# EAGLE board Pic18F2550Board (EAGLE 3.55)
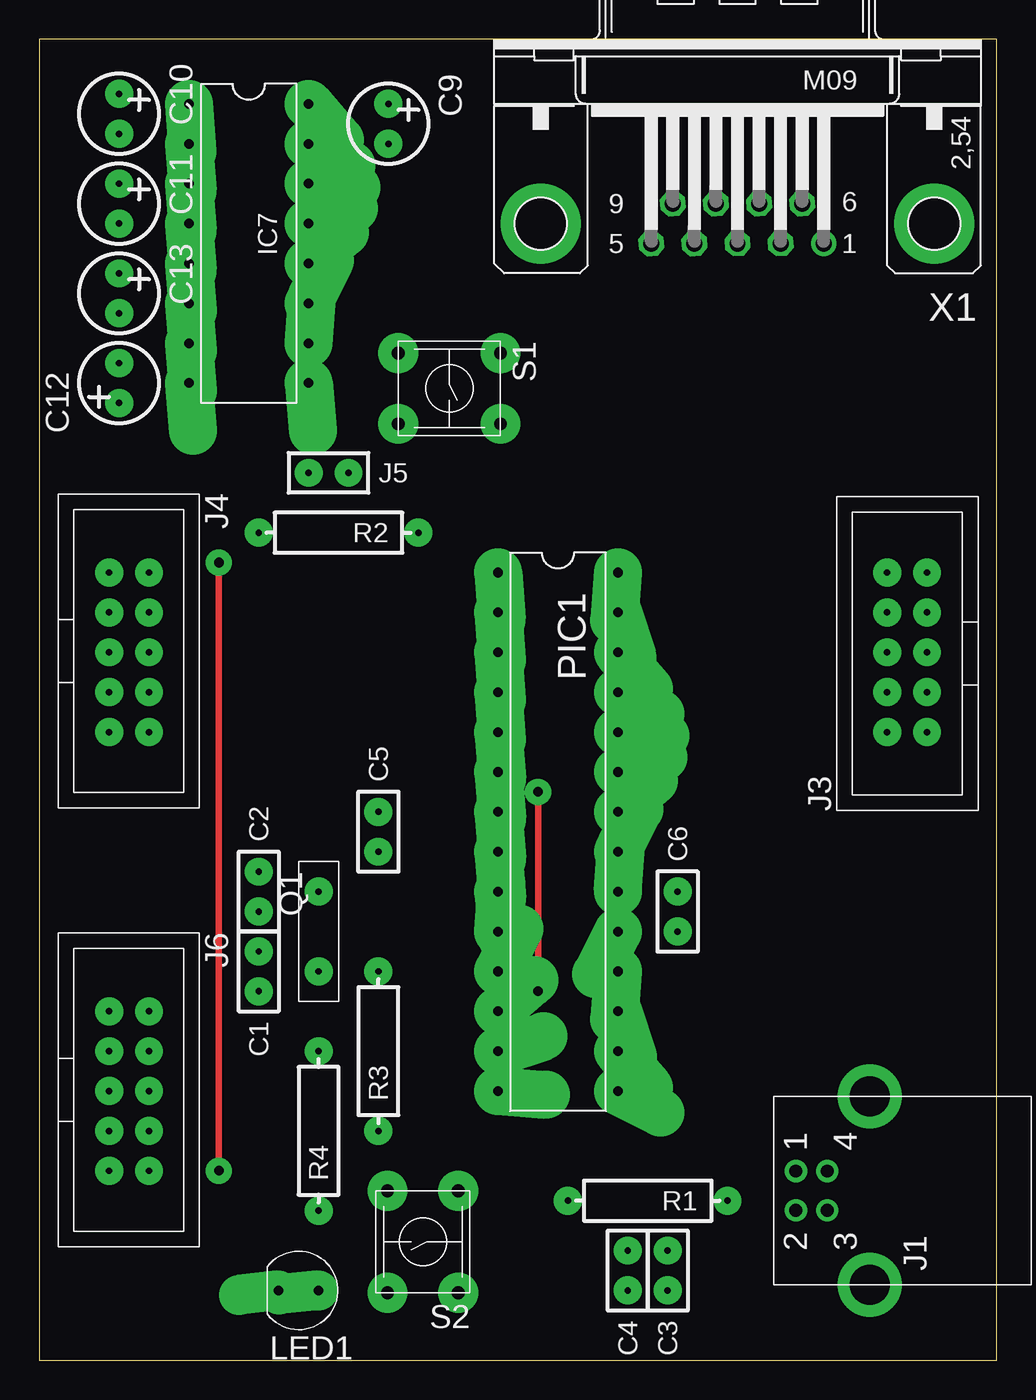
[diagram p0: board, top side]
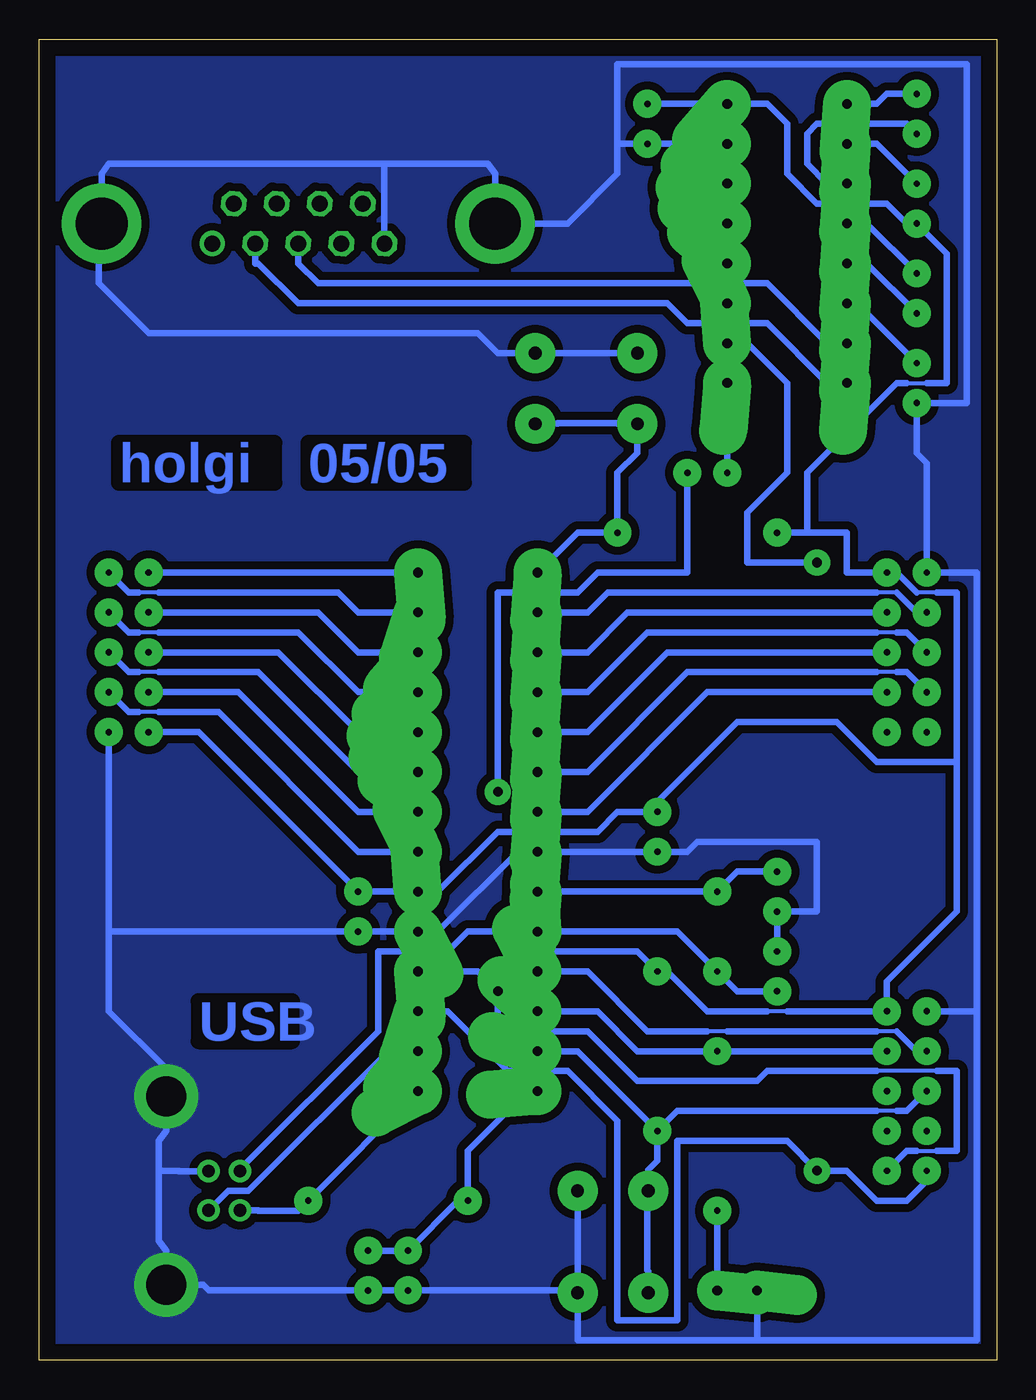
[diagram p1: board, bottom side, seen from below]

Size 60.94 x 84.12 mm. Coordinates in mm from the lower left corner, seen from the top.
Outline: 0,0 60.94,0 60.94,84.12 0,84.12 0,0
Copper layers used: Top, Bottom

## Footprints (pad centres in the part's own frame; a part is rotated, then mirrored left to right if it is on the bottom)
RM2,5 = drill 0.406 pad 1.778 round:  -1.27,0;  1.27,0
KO01 = drill 0.406 pad 1.778 round:  -1.27,0;  1.27,0
L-16B = drill 0.61 pad 3.048 offset:  -8.89,-3.81;  -6.35,-3.81;  6.35,-3.81;  8.89,-3.81;  -3.81,-3.81;  -1.27,-3.81;  3.81,-3.81;  1.27,-3.81;  8.89,3.81;  6.35,3.81;  3.81,3.81;  1.27,3.81;  -1.27,3.81;  -3.81,3.81;  -6.35,3.81;  -8.89,3.81
B_B = drill 2.54 pad 4.064 round: 1 6,-2.7; 2 -6,-2.7 | drill 0.813 pad 1.422 round:  1.25,0;  -1.25,0;  1.25,2;  -1.25,2
5 = drill 0.406 pad 1.778 round:  0,0;  2.54,0;  5.08,0;  7.62,0;  10.16,0;  10.16,2.54;  7.62,2.54;  5.08,2.54;  2.54,2.54;  0,2.54
MPER = drill 0.406 pad 1.778 round:  -1.27,0;  1.27,0
D_5MM = drill 0.61 pad 2.54 offset:  -1.27,0;  1.27,0
L-28SB = drill 0.61 pad 3.048 offset:  0,0;  2.54,0;  15.24,0;  17.78,0;  5.08,0;  7.62,0;  12.7,0;  10.16,0;  20.32,0;  22.86,0;  25.4,0;  27.94,0;  30.48,0;  33.02,0;  33.02,7.62;  30.48,7.62;  27.94,7.62;  25.4,7.62;  22.86,7.62;  20.32,7.62;  17.78,7.62;  15.24,7.62;  12.7,7.62;  10.16,7.62;  7.62,7.62;  5.08,7.62;  2.54,7.62;  0,7.62
ARZ_ST = drill 0.406 pad 1.778 round:  -2.54,0;  2.54,0
S04 = drill 0.406 pad 1.778 round:  -5.08,0;  5.08,0
US = drill 0.813 pad 2.54 round:  0,0;  4.5,0;  4.5,6.5;  0,6.5
9HP = drill 1.016 pad 1.6 octagon:  5.486,1.27;  2.743,1.27;  0,1.27;  -2.743,1.27;  4.115,-1.27;  1.372,-1.27;  -1.372,-1.27;  -4.115,-1.27 | drill 1.016 pad 1.6 round:  -5.486,1.27 | drill 3.302 pad 5.08 round:  -12.522,0;  12.522,0

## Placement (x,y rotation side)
C1  15p  [RM2,5]  13.97,24.77 270 top
C2  15p  [RM2,5]  13.97,29.84 90 top
C3  100n  [RM2,5]  40.01,5.71 270 top
C4  100n  [RM2,5]  37.47,5.71 270 top
C5  100n  [RM2,5]  21.59,33.66 90 top
C6  100n  [RM2,5]  40.64,28.57 90 top
C9  10u  [KO01]  22.23,78.74 270 top
C10  1u  [KO01]  5.08,79.38 270 top
C11  1u  [KO01]  5.08,73.66 270 top
C12  1u  [KO01]  5.08,62.23 90 top
C13  1u  [KO01]  5.08,67.94 270 top
IC7  MAX232  [L-16B]  13.34,71.12 270 top
J1  USB_B  [B_B]  50.16,10.79 90 top
J3  8BITPORT  [5]  56.52,40.01 90 top
J4  8BITPORT  [5]  4.45,50.16 270 top
J5  JUMPER  [MPER]  18.41,56.52 0 top
J6  8BITPORT  [5]  4.45,22.23 270 top
LED1  red  [D_5MM]  16.51,4.45 180 top
PIC1  18F2550  [L-28SB]  29.21,50.16 270 top
Q1  20.0MHz  [ARZ_ST]  17.78,27.3 270 top
R1  1k5  [S04]  38.73,10.16 180 top
R2  10k  [S04]  19.05,52.7 180 top
R3  47k  [S04]  21.59,19.68 90 top
R4  1k  [S04]  17.78,14.61 90 top
S1  Reset  [US]  22.86,64.14 270 top
S2  BOOTLOAD  [US]  26.67,10.79 180 top
X1  M09HP  [9HP]  44.45,72.39 180 top

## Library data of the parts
C1-C6 J3-J6 LED1 PIC1 Q1 R1-R4 S1 S2 = holg_plt
C9-C13 = holgnorm
IC7 = maxim
J1 = 8031bord
X1 = subd-a

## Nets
+5V: C5. C6. C9. C11. IC7. J1. J3. J4. J6. PIC1. R2. R3.
GND: C1. C2. C3. C4. C5. C6. C9. C12. IC7. J1. J1.1 J1.2 J3. J4. J6. LED1. PIC1. S1. S2. X1.
N$1: C3. C4. PIC1. R1.
N$2: C12. IC7.
N$3: C2. PIC1. Q1.
N$4: C1. PIC1. Q1.
N$7: LED1. R4.
N$8: J1. PIC1. R1.
N$9: J1. PIC1.
N$15: J3. PIC1.
N$16: PIC1. R2. S1.
N$17: J3. PIC1.
N$18: J3. PIC1.
N$19: J3. PIC1.
N$20: J3. PIC1.
N$21: J3. PIC1.
N$22: J3. PIC1.
N$23: J3. PIC1.
N$24: C11. IC7.
N$25: C10. IC7.
N$26: C13. IC7.
N$27: C10. IC7.
N$28: C13. IC7.
N$29: J4. PIC1.
N$30: J4. PIC1.
N$31: J4. PIC1.
N$32: J4. PIC1.
N$33: J4. PIC1.
N$34: J4. PIC1.
N$35: IC7. J5.
RC0: J6. PIC1.
RC1: J6. PIC1. R4.
RC2: J6. PIC1. R3. S2.
RXD: J5. J6. PIC1.
RXD_IN: IC7. X1.
TXD: IC7. J6. PIC1.
TXD_OUT: IC7. X1.

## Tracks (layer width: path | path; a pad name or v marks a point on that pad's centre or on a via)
+5V
  Bottom 0.254: 5.71,62.23 4.45,62.23 | 3.81,48.9 5.08,48.9 | 13.34,22.23 14.61,22.23
  Bottom 0.406: 22.23,80.01 IC7. 14.61,80.01 13.34,78.74 13.34,75.56 11.43,73.66 6.99,73.66 5.71,72.39 C11. 3.17,70.48 3.17,62.23 4.45,62.23 | 5.71,62.23 6.35,62.23 12.06,56.52 12.06,52.7 | 12.06,52.7 9.53,52.7 9.53,50.16 J4. 6.35,50.16 5.08,48.9 | 12.06,52.7 R2. | 3.81,48.9 2.54,48.9 2.54,38.1 | 2.54,38.1 2.54,28.57 6.99,24.13 J6. 13.34,22.23 | 2.54,38.1 7.62,38.1 10.16,40.64 16.51,40.64 21.59,35.56 C5. 24.13,34.92 25.4,33.66 31.75,33.66 35.56,29.84 36.83,29.84 C6. 50.8,40.01 J3. | 14.61,22.23 18.41,22.23 20.95,24.77 R3. 22.86,26.04 30.48,26.04 31.75,27.3 33.66,27.3 34.92,26.04 39.37,26.04 39.37,20.95 48.16,12.16 48.16,12.04
GND
  Bottom 0.406: 13.97,26.04 13.97,28.57 11.43,28.57 11.43,33.02 19.05,33.02 19.68,32.38 21.59,32.38 29.21,32.38 30.48,32.38 35.56,27.3 36.83,27.3 40.64,27.3 56.52,27.3 | 50.16,12.04 52.07,12.04 52.07,12.06 53.34,12.06 | 53.34,12.06 53.34,13.97 52.87,14.61 J1.1 52.87,18.57 56.52,22.23 56.52,27.3 | 17.14,77.47 C9. 24.13,77.47 | 24.13,77.47 24.13,82.55 1.91,82.55 1.91,60.96 5.08,60.96 5.08,57.78 4.45,57.15 4.45,50.16 1.27,50.16 1.27,22.23 | 24.13,77.47 24.13,75.56 27.3,72.39 X1. 31.93,75.56 32.38,76.2 38.73,76.2 | 38.96,71.12 38.96,76.2 38.73,76.2 | 38.73,76.2 56.52,76.2 56.97,75.56 56.97,72.39 56.97,70.03 57.15,69.85 57.15,68.58 53.98,65.41 33.02,65.41 31.75,64.14 S1. 22.86,64.14 | 53.34,12.06 53.34,7.62 52.87,6.99 J1.2 50.52,4.79 50.16,4.45 C3. C4. 27.94,4.45 27.79,4.29 S2. | 1.27,22.23 4.45,22.23 | S2. 26.67,10.79 | S2. 26.67,1.27 15.24,1.27 | 15.24,1.27 LED1. | 1.27,22.23 1.27,1.27 15.24,1.27 | 56.52,27.3 56.52,40.01
  pour Bottom (isolate 0.508): 0.64,0.64 0.64,83.19 60.33,83.19 60.33,0.64
N$1
  Bottom 0.406: 40.01,6.99 37.47,6.99 34.29,10.16 R1. 33.66,13.34 29.84,17.14 29.21,17.14
N$2
  Bottom 0.406: 9.53,67.31 8.89,67.31 C12.
N$3
  Bottom 0.406: C2. 16.51,31.11 17.78,29.84 29.21,29.84
N$4
  Bottom 0.406: C1. 16.51,23.5 Q1. 20.32,27.3 29.21,27.3
N$7
  Bottom 0.406: 17.78,4.45 17.78,9.53
N$8
  Bottom 0.406: 36.83,17.14 43.81,10.16 44.45,9.53 46.99,9.53 47.01,9.54 J1.
N$9
  Bottom 0.406: 50.16,9.54 50.15,9.54 48.9,10.79 47.62,10.79 38.73,19.68 36.83,19.68
N$15
  Bottom 0.406: PIC1. 53.98,50.16
N$16
  Bottom 0.406: 29.36,59.63 27.94,59.63 27.94,59.69 24.13,59.69 24.13,59.63 22.86,59.63 22.86,57.78 24.13,56.52 24.13,52.7 26.67,52.7 29.21,50.16
N$17
  Bottom 0.254: 53.34,48.9 54.61,48.9
  Bottom 0.406: 56.52,50.16 55.24,48.9 54.61,48.9 | 36.83,47.62 40.64,47.62 41.91,48.9 53.34,48.9
N$18
  Bottom 0.406: 36.83,45.09 40.64,45.09 43.18,47.62 53.98,47.62
N$19
  Bottom 0.254: 53.34,46.35 54.61,46.35
  Bottom 0.406: 36.83,42.55 40.64,42.55 44.45,46.35 53.34,46.35 | 56.52,47.62 55.24,46.35 54.61,46.35
N$20
  Bottom 0.406: 36.83,40.01 40.64,40.01 45.72,45.09 53.98,45.09
N$21
  Bottom 0.254: 53.34,43.81 54.61,43.81
  Bottom 0.406: 56.52,45.09 55.24,43.81 54.61,43.81 | 36.83,37.47 40.64,37.47 46.99,43.81 53.34,43.81
N$22
  Bottom 0.406: 36.83,34.92 40.64,34.92 48.26,42.55 53.98,42.55
N$23
  Bottom 0.254: 53.34,41.27 54.61,41.27
  Bottom 0.406: 56.52,42.55 55.24,41.27 54.61,41.27 | 36.83,32.38 40.64,32.38 49.53,41.27 53.34,41.27
N$24
  Bottom 0.406: 9.53,77.47 7.62,77.47 5.08,74.93
N$25
  Bottom 0.406: 9.53,74.93 10.79,74.93 12.06,76.2 12.06,78.11 11.43,78.74 5.71,78.74 C10.
N$26
  Bottom 0.406: 9.53,69.85 8.26,69.85 C13.
N$27
  Bottom 0.406: 9.53,80.01 7.62,80.01 6.99,80.64 5.08,80.64
N$28
  Bottom 0.406: 9.53,72.39 8.26,72.39 5.08,69.22
N$29
  Bottom 0.254: 6.35,48.9 7.62,48.9
  Bottom 0.406: 29.21,47.62 26.04,47.62 24.77,48.9 7.62,48.9 | 4.45,47.62 5.08,47.62 6.35,48.9
N$30
  Bottom 0.406: 29.21,45.09 26.04,45.09 23.5,47.62 6.99,47.62
N$31
  Bottom 0.254: 6.35,46.35 7.62,46.35
  Bottom 0.406: 4.45,45.09 5.71,46.35 6.35,46.35 | 29.21,42.55 26.04,42.55 22.23,46.35 7.62,46.35
N$32
  Bottom 0.406: 6.99,45.09 20.95,45.09 26.04,40.01 29.21,40.01
N$33
  Bottom 0.254: 6.35,43.81 7.62,43.81
  Bottom 0.406: 4.45,42.55 5.71,43.81 6.35,43.81 | 29.21,37.47 26.04,37.47 19.68,43.81 7.62,43.81
N$34
  Bottom 0.406: 29.21,34.92 26.04,34.92 18.41,42.55 6.99,42.55
N$35
  Bottom 0.406: 17.14,56.52 17.14,62.23
RC0
  Bottom 0.254: 6.35,20.95 7.62,20.95 | 17.14,20.95 18.41,20.95
  Bottom 0.406: 4.45,19.68 5.08,19.68 6.35,20.95 | 29.21,24.77 26.04,24.77 22.23,20.95 18.41,20.95 | 7.62,20.95 17.14,20.95
RC1
  Bottom 0.406: 6.99,19.68 R4. 22.86,19.68 25.4,22.23 29.21,22.23
RC2
  Bottom 0.254: 6.35,15.88 7.62,15.88
  Bottom 0.406: 4.45,17.14 5.71,15.88 6.35,15.88 | 21.59,14.61 20.32,15.88 7.62,15.88 | 29.21,19.68 26.67,19.68 21.59,14.61 | 21.59,14.61 21.59,12.7 22.17,12.12 22.17,10.79 22.17,9.58 22.23,9.53 22.23,5.71 22.17,5.66 22.17,4.29
RXD  (via drill 0.61 pad 1.68)
  Top 0.406: v31.75,23.5 v31.75,36.2
  Bottom 0.254: 3.81,18.41 7.62,18.41 | 5.08,13.34 3.81,13.34
  Bottom 0.406: 36.83,24.77 33.02,24.77 v31.75,23.5 31.75,20.95 26.04,20.95 22.86,17.78 15.24,17.78 14.61,18.41 7.62,18.41 | 3.81,18.41 2.54,18.41 2.54,13.34 3.81,13.34 | 6.99,12.06 5.71,13.34 5.08,13.34 | J5. 19.68,50.16 25.4,50.16 26.67,48.9 31.75,48.9 v31.75,36.2
RXD_IN
  Bottom 0.406: 9.53,62.23 10.79,62.23 14.61,66.04 19.68,66.04 20.95,67.31 44.45,67.31 46.99,69.85 47.19,69.85 47.19,71.12
TXD  (via drill 0.61 pad 1.68)
  Top 0.406: v11.43,12.06 v11.43,50.8
  Bottom 0.406: 4.45,12.06 4.45,11.43 5.71,10.16 7.62,10.16 9.53,12.06 v11.43,12.06 13.34,13.97 20.32,13.97 20.32,2.54 24.13,2.54 24.13,15.24 27.3,18.41 31.11,18.41 34.92,22.23 36.83,22.23 | 17.14,64.77 15.88,64.77 13.34,62.23 13.34,56.52 15.88,53.98 15.88,50.8 v11.43,50.8
TXD_OUT
  Bottom 0.406: 9.53,64.77 10.79,64.77 14.61,68.58 43.18,68.58 44.45,69.85 44.45,71.12

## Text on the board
Bottom: 05/05 | holgi | USB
